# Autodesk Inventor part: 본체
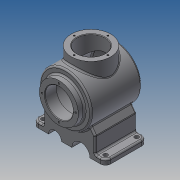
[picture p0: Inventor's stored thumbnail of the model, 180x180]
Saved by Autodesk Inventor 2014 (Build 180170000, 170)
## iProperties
Created: 2018-08
Part Number: 본체
Material: Generic
Document SubType Name: Modeling
Designer: kb542
Density: 1 g/cm^3
Appearance: Default
Author: kb542
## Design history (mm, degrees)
sketch "스케치1"
  geometry: L1 (-60, 0)-(60, 0); L2 (-60, 27)-(-60, 37.5); L3 (-60, 37.5)-(-48, 37.5); L4 (-48, 37.5)-(-48, 50); L5 (-60, 27)-(-38, 27); L6 (-38, 27)-(-38, 40); L7 (-38, 40)-(42.163, 40); L8 (-48, 50)-(48.671, 50); A1 r 116 centre (-56, 0) between (60, 0) and (48.671, 50); A2 r 106 centre (-56, 0) between (50, 0) and (42.163, 40); 3 further points
  constraints: 16 end point, 4 point on circle, 3 perpendicular, 2 centre point, 2 midpoint, 2 parallel, 2 point on line, 1 coincident, 1 horizontal, 1 vertical alignment
  dimensions: "d2" = 54 diameter of L5 L1; "d3" = 75 diameter of L3 L1; "d7" = 12 distance of L2.end L3.end; "d9" = 22 distance of L2.start L5.end; "d10" = 80 diameter of L7 L1; "d11" = 116 radius of A1; "d13" = 108 distance from line of L1.end L4; "d14" = 10 radial gap between concentric circles of A1 A2; "d15" = 100 diameter of L8 L1
revolve "회전1" sketch "스케치1" stored, may be unused: angle "d16" = 90 deg
node "작업 평면1"
sketch "스케치2"
  geometry: L1 (-41.103, -28.471)-(-50, -41.178); L2 (-50, -41.178)-(-50, -72); L3 (-50, -72)-(-70, -72); L4 (-70, -72)-(-70, -82); L5 (-70, -82)-(70, -82); L6 (70, -82)-(70, -72); L7 (70, -72)-(50, -72); L8 (50, -72)-(50, -41.178); L9 (50, -41.178)-(41.103, -28.471); A1 r 50 centre (0, 0) between (-41.103, -28.471) and (41.103, -28.471) reference; 2 further points
  constraints: 18 end point, 6 perpendicular, 2 horizontal alignment, 2 point on circle, 1 midpoint, 1 parallel, 1 vertical, 1 vertical alignment
  dimensions: "d18" = 82 distance from line of L5 point (0, 0); "d19" = 140 distance between parallel lines of L6 L4; "d22" = 35 deg angle of L9 L6; "d23" = 10 distance of L3.end L4.end; "d24" = 20 distance of L2.end L3.end; "d25" = 20 distance of L6.end L7.end; "d26" = 35 deg angle of L1 L4
extrude "돌출1" join sketch "스케치2" distance "d27" = 80; taper "d28" = 0 deg
sketch "스케치3"
  geometry: L1 (-70, -82)-(70, -82) reference; L2 (0, 0)-(0, -82); L3 (70, -82)-(-70, -82) reference; C1 r 12.5 at (-27.5, -82); C2 r 17.5 at (22.5, -82); A1 r 50 centre (0, 0) between (-41.103, -28.471) and (41.103, -28.471) reference
  constraints: 2 centre point, 2 end point, 2 point on line, 1 midpoint
  dimensions: "d29" = 27.5 distance of C1.centre L2.end; "d30" = 22.5 distance of C2.centre L2.end; "d31" = 17.5 radius of C2; "d32" = 12.5 radius of C1
extrude "돌출2" cut sketch "스케치3" stored distance "d33" = 80; taper "d34" = 0 deg
node "작업 평면2"
sketch "스케치5"
  geometry: L1 (-88, -120)-(-88, -20) reference; C1 r 38 at (-38, -70); 1 further point
  constraints: 1 centre point, 1 horizontal alignment
  dimensions: "d36" = 50 distance from line of C1.centre L1; "d37" = 76 diameter of C1
extrude "돌출3" join sketch "스케치5" stored distance "d38" = 80; taper "d39" = 0 deg
sketch "스케치6"
  geometry: C1 r 38 at (0, 0) reference; C2 r 27 at (0, 0); 1 further point
  constraints: 1 centre point, 1 coincident
  dimensions: "d40" = 54 diameter of C2
extrude "돌출4" cut sketch "스케치6" stored distance "d41" = 80; taper "d42" = 0 deg
node "작업 평면3"
fillet "모깎기1" dims "d47" = 10
fillet "모깎기2" dims "d48" = 3
chamfer "모따기1" distance "d49" = 1; stored, may be unused: second distance "d50" = 2, angle "d51" = 45 deg
sketch "스케치8"
  geometry: C1 r 38 at (0, 0) reference; 2 further points
  constraints: 1 vertical alignment
  dimensions: "d52" = 32.5 distance of C1.centre point (0, 32.5)
hole "구멍1" sketch "스케치8" at (0, 32.5) diameter "d53" = 3.242; stored, may be unused: countersink angle "d57" = 90 deg, drill point angle "d59" = 118 deg; dims "d54" = 8, "d55" = 4, "d56" = 2, "d58" = 10
sketch "스케치9"
  geometry: C1 r 37.5 at (0, 0) reference; 1 further point
  constraints: 1 vertical alignment
  dimensions: "d63" = 32.5 distance of C1.centre point (0, 32.5)
hole "구멍2" sketch "스케치9" at (0, 32.5) diameter "d64" = 3.242; stored, may be unused: countersink angle "d68" = 90 deg, drill point angle "d70" = 118 deg; dims "d65" = 8, "d66" = 4, "d67" = 2, "d69" = 10
fillet "모깎기3" dims "d74" = 3
fillet "모깎기4" dims "d75" = 3
fillet "모깎기5" dims "d76" = 3
node "작업 평면4"
sketch "스케치11"
  geometry: C1 r 32.5 at (0, 0); 1 further point
  constraints: 1 centre point, 1 coincident, 1 other
  dimensions: "d77" = 65 diameter of C1
feature "엠보싱2" sketch "스케치11" dims "d2" = 54, "d3" = 75, "d7" = 12, "d9" = 22, "d10" = 80, "d11" = 116, "d13" = 108, "d14" = 10, "d15" = 100, "d18" = 82, "d19" = 140, "d22" = 35 deg, "d23" = 10, "d24" = 20, "d25" = 20, "d26" = 35 deg, "d78" = 0.5, "d79" = 0
hole "구멍3" diameter "d82" = 8; stored, may be unused: countersink angle "d86" = 90 deg, drill point angle "d88" = 118 deg; dims "d80" = 10, "d81" = 10, "d83" = 8, "d84" = 4, "d85" = 2, "d87" = 10
hole "구멍4" diameter "d91" = 8; stored, may be unused: countersink angle "d95" = 90 deg, drill point angle "d97" = 118 deg; dims "d89" = 10, "d90" = 10, "d92" = 8, "d93" = 4, "d94" = 2, "d96" = 10
hole "구멍5" diameter "d100" = 8; stored, may be unused: countersink angle "d104" = 90 deg, drill point angle "d106" = 118 deg; dims "d98" = 10, "d99" = 10, "d101" = 8, "d102" = 4, "d103" = 2, "d105" = 10
hole "구멍6" diameter "d109" = 8; stored, may be unused: countersink angle "d113" = 90 deg, drill point angle "d115" = 118 deg; dims "d107" = 10, "d108" = 10, "d110" = 8, "d111" = 4, "d112" = 2, "d114" = 10
node "솔리드1"
pattern_circular "원형 패턴1" dims angle "d61" = 360 deg
pattern_circular "원형 패턴2" dims angle "d72" = 360 deg
other parameters: "d17" = -8, "d35" = -147, "d43" = -54
